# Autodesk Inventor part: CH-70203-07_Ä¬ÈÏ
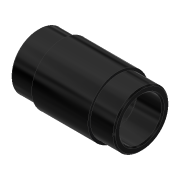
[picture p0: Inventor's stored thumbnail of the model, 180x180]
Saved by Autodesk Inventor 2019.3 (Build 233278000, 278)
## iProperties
Created: 2010-06
Part Number: CH-70203-07_Ä¬ÈÏ
Material: Ogólny
Document SubType Name: Modeling
Designer: CADENGINEERING4
Density: 1 g/cm^3
Appearance: Gładki — czarny
Author: CADENGINEERING4
Revision Number: ÈÎºÎ
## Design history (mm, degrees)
feature "NONE"
node "Bryła1"
